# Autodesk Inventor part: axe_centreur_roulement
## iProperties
Created: 2011-01
Part Number: axe_centreur_roulement
Document SubType Name: Modeling
Designer: eric
Density: 1 g/cm^3
Mass: 0.187365 g
Surface Area: 3.32261 cm^2
Volume: 0.187365 cm^3
Author: eric
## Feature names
1. Base1
